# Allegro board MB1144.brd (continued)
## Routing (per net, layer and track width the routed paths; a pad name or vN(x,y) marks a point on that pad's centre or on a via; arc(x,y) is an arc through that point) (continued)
NETCN12_12: length 118.4
  TOP w0.127: CN12.12 109.32,81.15 109.69,81.52 U18.4 111.08,81.04 111.6,80.52 112.49,80.52 113.25,79.76 113.25,73.15 112.26,72.16 88.33,72.16 85.95,74.55 61.11,74.55 60.29,73.74 55.9,73.74 55.57,73.41 52.9,73.41 52.39,72.9 50.79,72.9 50.23,72.34 v1(50.21,72.34) ; v1(49.88,107.57) 49.75,107.7 SB26.2
  BOTTOM w0.127: v1(49.88,107.57) 51.94,105.51 51.94,94.28 49.88,92.23 49.88,84.96 51.94,82.91 51.94,76.86 50.21,75.13 v1(50.21,72.34)
NETCN12_14: length 18.2
  TOP w0.127: v1(110,71.45) 110,71.53 110.33,71.86 112.67,71.86 113.71,72.9 R162.1 ; v1(109.82,77.22) 110.19,76.85 U19.5 ; CN12.14 v1(109.32,79.88) R154.1
  BOTTOM w0.127: v1(110,71.45) 109.82,71.63 v1(109.82,77.22) 109.82,79.38 v1(109.32,79.88)
NETCN12_16: length 26.9
  TOP w0.127: U19.4 111.87,77.07 R156.1 110.33,78.61 v1(109.32,78.61) CN12.16 ; R131.1 113.96,89.59 113.96,89.92 112.82,91.06 111.19,91.06 110.56,90.42 107.92,90.42 v1(107.82,90.32)
  BOTTOM w0.127: v1(107.82,90.32) 107.26,89.76 107.26,81.18 109.32,79.12 v1(109.32,78.61)
NETCN12_18: length 116.3
  TOP w0.127: v1(49.47,73.58) 49.5,73.58 49.57,73.66 52.01,73.66 52.52,74.17 55.19,74.17 55.54,74.52 59.58,74.52 60.37,75.31 86.71,75.31 88.74,73.28 111.35,73.28 111.87,73.8 U19.3 111.87,75.55 111.47,75.95 109.95,75.95 108.55,77.34 107.41,77.34
  BOTTOM w0.127: v1(49.47,73.58) 49.52,73.63 49.52,75.64 49.93,76.05 49.93,84.15 49.37,84.71 49.37,92.94 49.9,93.47 49.9,101.83 49.24,102.49 49.24,107.95 51.4,110.11 55.85,110.11 57.15,111.41 57.15,111.99
NETCN12_20: length 112.5
  TOP w0.127: v1(48.81,73.58) 49.4,74.17 50.16,74.17 50.41,73.91 51.89,73.91 52.39,74.42 55.06,74.42 55.42,74.78 59.46,74.78 60.24,75.56 87.12,75.56 89.07,73.61 110.03,73.61 110.57,74.15 U19.1 110.57,75.45 110.33,75.69 109.44,75.69 109.06,76.07 CN12.20
  BOTTOM w0.127: SB39.2 55.21,111 54.71,110.49 51.02,110.49 48.86,108.33 48.86,102.49 49.65,101.7 49.65,93.6 49.12,93.07 49.12,84.58 49.68,84.02 49.68,76.43 49.07,75.82 49.07,73.84 v1(48.81,73.58)
NETCN13_1: length 13.3
  BOTTOM w0.508: JP15.6 12.97,77.77 7.11,77.77 6.78,78.11 3.91,78.11 CN13.1
NETCN13_2: length 211.7
  TOP w0.279: 19.4,94.87 19.52,94.75 U12.7
  TOP w0.381: U10.13 v1(107.58,107.97)
  TOP w0.508: 19.4,94.87 16.3,94.87 12.87,98.3 6.06,98.3 5.2,97.44 U11.3 3.09,97.44 2.41,96.75 2.41,90.35 1.29,89.23 1.29,76.45 2.31,75.44 3.78,75.44 CN13.2 ; v1(68.83,59.74) 40.33,59.74 37.51,56.92 28.06,56.92 v1(22.45,51.31)
  BOTTOM w0.508: CN13.2 10.46,76.96 11.45,75.97 11.45,68.91 12.92,67.44 12.92,64.52 22.45,54.99 v1(22.45,51.31) ; v1(68.83,59.74) 79.98,59.74 92.6,72.36 101.26,72.36 103.68,74.78 103.68,87.58 105.35,89.26 105.35,96.24 107.11,97.99 107.11,104.06 106.83,104.34 106.83,107.21 v1(107.58,107.97)
NETCN14_2: length 40.6
  TOP w0.127: CN18.3 17.61,51.32 R178.2 18.26,51.94 19.78,51.94 20.03,52.2 20.03,52.32 27.02,59.31 27.02,77.6 30.07,80.64 33.02,80.64
NETCN14_4: length 2.4
  TOP w0.127: R140.2 35.56,81.82 35.56,80.64
NETCN14_6: length 2.7
  TOP w0.127: R141.2 37.31,81.44 38.1,80.64
NETCN14_8: length 3.1
  TOP w0.127: 40.64,80.64 40.64,81.38 R142.2
NETCN14_10: length 46.2
  TOP w0.381: R158.1 13.61,77.77 17.11,77.77 18.71,79.38 26.44,79.38 33.34,86.28 38.65,86.28 40.1,84.84 40.1,83.69 43.15,80.64 43.18,80.64
  TOP w0.508: R158.1 12.16,76.58 JP15.5 JP15.3 JP15.1
NETCN14_12: length 2.9
  TOP w0.127: R143.2 45.72,81.82 45.72,80.64
NETCN14_14: length 2.9
  TOP w0.127: 48.26,80.64 48.26,81.82 R144.2
NETCN14_16: length 2.9
  TOP w0.127: 50.8,80.64 52.04,81.88 R145.2
NETCN14_18: length 2.8
  TOP w0.127: 53.34,80.64 53.34,82.07 R146.2
NETCN14_20: length 2.9
  TOP w0.127: R147.2 55.88,81.82 55.88,80.64
NETCN14_22: length 2.9
  TOP w0.127: R148.2 58.42,81.82 58.42,80.64
NETCN14_32: length 3
  TOP w0.127: R151.2 71.12,81.57 71.12,80.64
NETCN14_40: length 94.6
  TOP w0.127: U2.A1 82.9,150.74 82.9,146.38 85.67,143.61 88,143.61 90.11,141.5 v1(91.1,141.5) ; 81.28,80.64 82.04,80.64 82.92,81.53 85.34,81.53 87.45,83.64 87.45,85.24 88.49,86.28 88.49,90.42 87.98,90.93 v1(87.98,91.19)
  BOTTOM w0.127: v1(87.98,91.19) 88.23,91.19 89.38,92.33 93.82,92.33 98.14,96.65 98.14,99.44 100.11,101.41 100.11,109.41 100.68,109.98 100.68,135.03 98.16,137.54 94.66,137.54 91.1,141.1 v1(91.1,141.5)
NETCN14_42: length 92.7
  TOP w0.127: 83.82,80.64 84.96,80.64 87.83,83.52 87.83,85.14 89,86.31 89,90.3 89.5,90.81 v1(89.76,90.81) ; v1(92.04,141.63) 91.94,141.63 91.61,141.96 90.27,141.96 88.08,144.15 86.58,144.15 85.79,144.93 85.79,145.29 85.72,145.36 85.72,145.54 83.66,147.6 83.66,150.24 84.04,150.62 84.04,151.18 U2.B2
  BOTTOM w0.127: v1(89.76,90.81) 92.17,90.81 92.93,91.57 94.46,91.57 99.03,96.14 99.03,99.06 100.88,100.91 100.88,109.07 101.44,109.63 101.44,135.38 98.52,138.3 95.09,138.3 92.04,141.35 v1(92.04,141.63)
NETCN14_44: length 3.3
  TOP w0.127: R149.2 86.36,80.8 86.36,80.64
NETCN14_46: length 3.5
  TOP w0.127: R150.2 90.9,82.14 89.41,80.64 88.9,80.64
NETCN15_3: length 30.4
  TOP w0.127: v1(109.87,85.8) 110.19,86.12 RS1.6 ; R126.1 R131.2 118.71,86.36 CN15.3 122.02,84.99 122.02,80.9 121.25,80.14 113.66,80.14 112.74,81.05 112.74,82.04 111.87,82.92 U18.1 111.87,83.71 112.26,84.1 v1(112.26,84.33)
  BOTTOM w0.127: v1(109.87,85.8) 111.17,85.8 112.26,84.71 v1(112.26,84.33)
NETCN15_11: length 5.9
  TOP w0.127: R157.1 116.3,77.6 R159.2 CN15.11
NETCN15_17: length 4
  TOP w0.127: R163.2 CN15.17
NETCN15_19: length 4.1
  TOP w0.127: CN15.19 120.4,66.29 R164.2
NETCN17_2: length 6.3
  TOP w0.155: R180.2 112.68,50.36 113.19,50.36 113.81,50.98 113.81,51.58 114.34,52.11 115.61,52.11 115.76,51.96 115.76,51.28 115.46,50.98 CN17.2
NETCN17_3: length 8
  TOP w0.155: R177.2 R179.2 112.68,50.74 113.03,50.74 113.43,51.14 113.43,51.74 114.18,52.49 115.76,52.49 116.14,52.12 116.14,51.23 116.4,50.98 CN17.3
NETCN18_1: length 48.4
  TOP w0.127: CN18.1 17.54,53.52 R175.2 18.7,54.67 21.29,54.67 26.38,59.77 26.38,78.46 33.65,85.72 37.81,85.72 R142.1
NETCN18_2: length 47
  TOP w0.127: CN18.2 17.59,52.42 R176.2 18.26,53.09 20.34,53.09 26.77,59.51 26.77,78.36 33.78,85.37 36.52,85.37 R141.1
NETCN18_5: length 49.7
  TOP w0.127: R140.1 34.13,83.19 34.13,80.14 33.5,79.5 30.09,79.5 27.78,77.19 27.78,58.93 20.42,51.56 20.42,48.64 20.16,48.39 16.99,48.39 16.26,49.12 CN18.5
NETCN18_7: length 70.9
  TOP w0.127: R147.1 58.01,83.69 58.01,82.8 57.12,81.92 57.12,77.85 56.39,77.13 54.34,77.13 53.92,76.71 50.26,76.71 49.5,75.95 44.29,75.95 43.78,75.44 34.37,75.44 33.86,74.93 32.86,74.93 28.8,70.87 28.8,58.8 21.3,51.31 21.3,48.39 20.54,47.62 18.13,47.62 R182.2 17.42,46.92 CN18.7
NETCN18_8: length 71.9
  TOP w0.127: R148.1 58.52,83.44 58.52,82.68 57.5,81.66 57.5,77.85 56.51,76.86 54.45,76.86 54.04,76.45 50.39,76.45 49.63,75.69 44.42,75.69 43.91,75.18 34.64,75.18 34,74.55 32.99,74.55 29.05,70.61 29.05,58.67 21.56,51.18 21.56,48.01 20.16,46.61 18.26,46.61 R185.2 17.46,45.82 CN18.8
NETCN18_10: length 2.9
  TOP w0.127: R194.2 7.08,41.81 CN18.10
NETCN19_23: length 10.1
  TOP w0.127: T6.3 92.04,38.61 92.42,38.23 v1(92.93,38.23) 93.82,38.23 R259.2
  BOTTOM w0.127: v1(92.93,38.23) 96.48,34.68 CN19.23
NETCN19_31: length 12.5
  TOP w0.127: U32.16 98.76,20.44 99.66,21.34 99.66,23.58 CN19.31
NETCN19_32: length 16.2
  TOP w0.127: CN19.32 102.46,23.33 102.46,20.95 100.44,18.93 U32.13
NETCN19_33: length 8.7
  TOP w0.127: CN19.33 97.92,21.17 U32.1
NETCN19_34: length 11
  TOP w0.127: U32.15 91.79,19.93 91.92,20.07 99.35,20.07 CN19.34
NETCN20_2: length 3.5
  TOP w0.203: R192.2 124.43,42.42 125.95,40.9 CN20.2
NETCN20_3: length 4
  TOP w0.203: CN20.3 123.05,40.37 122.02,41.4 121.13,41.4 R191.1
NETCN21_2: length 3.5
  TOP w0.203: CN21.2 125.95,27.06 124.3,28.7 R221.1
NETCN21_3: length 4
  TOP w0.203: CN21.3 123.05,26.53 121.89,27.69 121.13,27.69 R220.1
NETCN21_4: length 44.4
  TOP w0.203: CN21.4 121.18,18.29 107.16,18.29 105.12,20.32 105.12,23.88 103.35,25.65 98.14,25.65 97.12,24.64 84.42,24.64 83.28,25.78 R227.1
NETCN21_6: length 25.7
  TOP w0.203: R225.2 90.39,25.27 96.74,25.27 97.63,26.16 113.66,26.16 CN21.6
NETCN22_1: length 10.5
  TOP w0.508: 9.44,21.59 CN22.1 ; CN22.1 11.83,21.59 ; CN22.1 10.64,19.3 ; CN22.1 10.64,23.88 ; U31.1 17.62,22.61 ; U31.1 17.62,21.65 ; U31.1 16.34,22.13 ; U31.1 18.9,22.13
NETCN23_2: length 3.4
  TOP w0.127: v1(69.69,27.36) U30.16
  BOTTOM w0.127: CN23.2 71.09,28.5 69.95,27.36 v1(69.69,27.36)
NETCN23_3: length 5.7
  TOP w0.127: U30.15 70.96,27.61 v1(69.69,26.34)
  BOTTOM w0.127: CN23.3 68.55,27.48 v1(69.69,26.34)
NETCN23_4: length 10.9
  TOP w0.127: v1(66.77,22.86) 69.69,19.94 U30.13
  BOTTOM w0.127: CN23.4 66.01,23.62 v1(66.77,22.86)
NETCN23_7: length 25.7
  TOP w0.127: v1(62.93,4.22) 62.93,10.64 64.36,12.06 66.39,12.06 68.04,13.72 68.04,17.14 67.15,18.03 U30.11
  BOTTOM w0.127: v1(62.93,4.22) 64.71,2.44 67.05,2.44 68.55,3.94 CN23.7
NETCN23_8: length 20.5
  TOP w0.127: v1(63.7,4.32) 63.7,10.41 64.84,11.56 66.77,11.56 68.42,13.21 68.42,19.21
  BOTTOM w0.127: CN23.8 66.01,3.95 66,3.94 64.08,3.94 v1(63.7,4.32)
NETCN23_18: length 13.5
  TOP w0.127: v1(58.39,23.62) 59.79,22.23 63.72,22.23 64.61,21.34 U30.9 64.61,17.78 R242.2
  BOTTOM w0.127: v1(58.39,23.62) CN23.18
NETD3_1: length 2.2
  TOP w0.127: R59.1 41.62,126.22 D3.1
NETD3_2: length 2.8
  TOP w0.127: D3.2 40.12,123.17 JP8.2
NETD4_1: length 2.2
  TOP w0.127: D4.1 JP9.2
NETD4_2: length 9.5
  TOP w0.127: R93.1 106.65,112.09 106.6,112.14 v1(106.6,112.17) 106.57,112.17 105.71,113.03 D4.2 ; U10.16 v1(106.6,107.97)
  BOTTOM w0.127: v1(106.6,112.17) 106.78,111.99 106.78,108.14 v1(106.6,107.97)
NETJP4_2: length 13.3
  TOP w0.127: JP4.2 17.49,137.54 R45.1 17.11,134.37 15.84,133.1 15.84,128.91 16.73,128.02 U8.8
NETJP4_3: length 2.9
  TOP w0.127: R46.1 20.03,138.68 JP4.3
NETJP5_1: length 144.2
  TOP w0.508: v1(111.42,126.92) 110.84,127.51 110.84,131.44 109.44,132.84 108.43,132.84 JP5.1
  BOTTOM w0.508: RV3.2 104.87,39.27 112.9,47.29 112.9,57.12 116.78,61.01 116.78,69.62 117.01,69.85 117.01,70.89 118.28,72.16 118.28,87.76 116.3,89.74 111.78,89.74 110.03,91.49 110.03,93.52 110.79,94.28 110.79,100.38 111.12,100.71 111.12,108.31 110.46,108.97 110.46,114.81 110.79,115.14 110.79,123.11 111.42,123.75 v1(111.42,126.92)
NETJP5_2: length 4.4
  BOTTOM w0.508: JP5.2 JP7.2
NETJP5_3: length 8.9
  TOP w0.508: R51.1 R52.2 JP5.3
NETJP6_1: length 3.2
  TOP w0.127: R55.2 JP6.1
NETJP7_1: length 2.4
  TOP w0.508: R63.1 JP7.1
NETJP10_2: length 6
  TOP w0.508: L1.1 94.96,104.65 JP10.2
NETJP11_4: length 63.5
  TOP w0.127: R123.1 55.21,90.17 54.34,89.3 U15.12 47.47,89.3 45.58,91.19 38.83,91.19 38.07,90.42 36.93,90.42 36.42,89.92 31.97,89.92 30.7,88.65 27.53,88.65 26.89,89.28 22.78,89.28 v1(22.68,89.19) ; R123.1 57.63,90.81 T2.5 T2.2 ; R123.1 57.31,89.86 T2.6 T2.1
  BOTTOM w0.127: v1(22.68,89.19) 19.83,92.04 19.83,96.72 19.15,97.41 19.15,102.87 17.88,104.14 JP11.4
NETJP12_2: length 66.4
  TOP w0.127: v1(18.13,102.74) 18.76,103.38 18.76,105.26 20.03,106.53 34.56,106.53 v1(34.66,106.43) ; U7.6 57.25,118.87 56.1,120.02 v1(55.34,120.02)
  BOTTOM w0.127: JP12.2 22.57,88.49 18.64,92.43 18.64,102.23 v1(18.13,102.74) ; v1(34.66,106.43) 35.5,106.43 42.61,113.54 48.86,113.54 v1(55.34,120.02)
NETJP13_2: length 75.2
  TOP w0.102: U5.B4 99.06,145.67 96.87,145.67
  TOP w0.127: JP13.2 R133.2 98.77,90.17 v1(97.5,91.44) ; v4(93.87,144.3) 95.09,144.3 96.46,145.67 96.87,145.67
  BOTTOM w0.127: v1(97.5,91.44) 97.5,93.34 100.04,95.89 100.04,98.81 101.67,100.43 101.67,108.53 102.2,109.07 102.2,135.74 98.88,139.06 95.6,139.06 93.06,141.6 93.06,143.79 93.57,144.3 v4(93.87,144.3)
NETJP14_1: length 92.2
  TOP w0.089: U29.C6 79.48,30.24 78.09,30.24 77.82,29.97
  TOP w0.127: 77.82,29.97 77.29,29.44 77.29,29.08 76.65,28.45 v1(76.55,28.45)
  BOTTOM w0.127: v1(76.55,28.45) 76.27,28.45 72.97,31.75 71.04,31.75 70.66,32.13 56.92,32.13 42.89,46.15 42.89,62.23 35.91,69.22 29.94,69.22 26.23,72.92 26.23,78.64 25.11,79.76 JP14.1
NETJP14_2: length 174.8
  TOP w0.127: v1(9.02,11.21) 9.96,12.15 U36.3 ; v1(94.71,13.69) 94.71,13.72 95.68,14.69 U35.3
  BOTTOM w0.127: v1(94.71,13.69) 92.75,13.69 89.6,10.54 30.19,10.54 27.27,7.62 18.84,7.62 14.37,12.09 10.66,12.09 9.79,11.21 v1(9.02,11.21) 9.02,13.5 14.07,18.54 14.07,20.95 26.89,33.78 26.89,67.31 22.07,72.14 22.07,75.95 21.56,76.45 21.56,81.28 JP14.2
NETJP15_2: length 147.4
  TOP w0.127: U10.17 106.7,107.32 107.66,106.35 v1(107.66,106.35) ; JP15.2 18.38,80.9 26.51,80.9 27.27,81.66 v1(27.27,81.97) ; v1(30.5,70.79) 31.59,71.88 50.41,71.88 51.17,72.64 52.52,72.64 53.03,73.15 55.7,73.15 56.03,73.48 60.42,73.48 61.23,74.3 85.54,74.3 88.59,71.25 v1(107.64,71.25)
  BOTTOM w0.127: v1(27.27,81.97) 27.35,81.89 27.35,74.35 30.5,71.2 v1(30.5,70.79) ; v1(107.66,106.35) 108.05,105.97 108.05,96.72 106.65,95.33 106.65,94.41 105.94,93.7 105.94,89.81 106.65,89.1 106.65,80.19 107.64,79.2 v1(107.64,71.25)
NETJP19_1: length 55
  TOP w0.127: R145.1 52.29,84.58 52.98,83.9 52.98,82.04 52.06,81.13 52.06,80.26 51.56,79.76 50.34,79.76 49.35,78.77 49.35,77.88 48.71,77.24 41.04,77.24 40,76.2 29.38,76.2 v1(29.36,76.23)
  BOTTOM w0.127: JP19.1 25.47,98.96 25.47,93.37 28.87,89.97 28.87,76.66 29.31,76.23 v1(29.36,76.23)
NETJP19_2: length 66.3
  TOP w0.127: R21.2 19.98,157.42 v1(20.67,157.42) U1.4
  BOTTOM w0.127: JP19.2 22.57,100.84 24.35,102.62 25.37,102.62 26.09,103.34 26.09,109.52 24.86,110.74 24.86,124.21 25.19,124.54 25.19,126.82 22.78,129.24 22.78,132.87 23.69,133.78 23.69,141.01 25.37,142.68 25.37,152.53 20.67,157.23 v1(20.67,157.42)
NETL4_2: length 3.6
  TOP w0.508: R223.2 R219.2 L4.2
NETLD1_2: length 2.5
  TOP w0.127: LD1.2 R258.2
NETLD2_2: length 2.5
  TOP w0.127: LD2.2 R257.2
NETLD3_2: length 2.5
  TOP w0.127: LD3.2 R256.2
NETLD4_2: length 2.5
  TOP w0.127: LD4.2 R255.2
NETLD5_1: length 1.6
  TOP w0.127: LD5.1 23.08,164.85 R6.2
NETLD5_2: length 2.9
  TOP w0.127: LD5.2 21.43,167.26 21.18,167.51 T1.3
NETLD6_1: length 1.3
  TOP w0.127: 22.96,162.43 LD6.1
NETLD6_2: length 125.7
  TOP w0.127: U1.3 21.37,159.83 20.8,160.4 v1(20.8,160.78) 20.8,161.67 21.43,162.43 LD6.2 ; R109.2 54.71,100.46 54.71,97.66 54.25,97.21 50.51,97.21 49.85,96.55 49.85,95.12 49.09,94.36 47.97,94.36 47.09,93.47 31.08,93.47 28.92,91.31 17.24,91.31 v1(17.11,91.44)
  BOTTOM w0.127: v1(17.11,91.44) 17.05,91.5 17.05,101.85 15.97,102.94 15.97,105.28 17.05,106.37 17.05,108.11 20.54,111.6 20.54,111.63 23.72,114.81 23.72,126.21 22.27,127.66 22.27,141.43 24.99,144.15 24.99,152.4 20.16,157.23 20.16,157.73 20.92,158.5 20.92,160.66 v1(20.8,160.78)
NETLD7_1: length 1.8
  TOP w0.127: R165.1 LD7.1
NETLD8_2: length 2
  TOP w0.127: LD8.2 18.01,7.38 R253.2
NETLD8_3: length 1.8
  TOP w0.127: R254.2 19.51,7.74 LD8.3
NETLD8_4: length 6.8
  TOP w0.127: LD8.4 19.51,4.2 18.64,5.08 17.37,5.08 16.86,5.59 16.86,7.75 R252.1
NETLD9_1: length 45.4
  TOP w0.127: R268.2 80.23,48.77 80.23,43.43 80.87,42.8 92.5,42.8 96.87,38.43 96.87,36.47 97.68,35.66 103.65,35.66 111.09,43.1 LD9.1
NETLD9_2: length 48.5
  TOP w0.127: LD9.2 109.57,42.42 103.12,35.97 97.92,35.97 97.2,36.69 97.2,38.56 92.58,43.18 81.12,43.18 80.74,43.56 80.74,47.24 81.12,47.62 U37.8 82.73,49.19 81.12,50.8 R110.2
NETR1_2: length 2.6
  TOP w0.127: R261.2 R1.2 23.49,166.12 T1.1
NETR18_1: length 9.9
  TOP w0.102: 83.28,155.07 83.28,154.19 U2.B5
  TOP w0.127: 83.28,155.07 80.74,157.61 R22.2 R18.1
NETR23_2: length 1.8
  TOP w0.127: U3.15 7.14,155.25 R23.2
NETR24_1: length 122.6
  TOP w0.127: v1(28.84,75.12) 29.64,75.12 30.47,75.95 40.25,75.95 41.29,76.99 48.91,76.99 49.63,77.7 49.63,78.61 50.44,79.43 54.25,79.43 54.58,79.76 54.58,81.15 55.34,81.92 55.34,83.57 R146.1 ; R24.1 v1(23.72,155.32)
  BOTTOM w0.127: v1(28.84,75.12) 28.77,75.18 28.77,75.64 28.37,76.05 28.37,89.64 24.78,93.22 24.78,97.23 23.72,98.3 23.72,100.46 26.34,103.08 26.34,109.64 25.11,110.87 25.11,123.98 25.47,124.33 25.47,127.13 23.11,129.49 23.11,132.82 24.07,133.78 24.07,140.85 25.75,142.52 25.75,152.73 23.72,154.76 v1(23.72,155.32)
NETR24_2: length 1.7
  TOP w0.127: R24.2 20.34,155.01 U4.15
NETR25_2: length 5
  TOP w0.102: 104.06,151.13 104.06,149.66 103.46,149.06 U5.F7
  TOP w0.127: 104.06,151.13 104.06,153.75 R25.2
NETR29_2: length 3.3
  TOP w0.254: U4.6 20.34,148.66 R31.1 21.18,147.83 R29.2
NETR30_2: length 9.4
  TOP w0.254: U4.5 19.69,149.14 18.89,148.34 R30.2 19.65,147.83 R31.2 ; U4.8 21.64,149.1 21.9,148.84 v1(21.94,148.84)
  BOTTOM w0.254: v1(21.94,148.84) 20.92,147.83 R30.2
NETR32_2: length 106.6
  TOP w0.102: 96.87,146.06 U5.A4
  TOP w0.127: v1(91.99,143.97) 92.75,143.97 R32.2 95.35,145.03 96.37,146.06 96.87,146.06 ; 46.83,131.84 46.83,145.67 v1(47.06,145.9) ; v1(88.61,141.73) 88.23,141.73 87.09,142.88 84.93,142.88 76.3,151.51 76.3,160.78 74.19,162.89 71.34,162.89 v1(69.98,164.25)
  BOTTOM w0.127: v1(47.06,145.9) 49.86,145.9 53.13,149.17 53.13,159.38 52.7,159.82 52.7,160.55 54.48,162.33 54.48,166.09 54.86,166.47 64.18,166.47 64.74,167.03 64.74,168.55 65.14,168.96 69.16,168.96 69.72,168.4 69.72,164.52 v1(69.98,164.25) ; v1(91.99,143.97) 91.99,143.36 90.37,141.73 v1(88.61,141.73)
NETR33_2: length 6.8
  TOP w0.127: U7.97 60.25,140.76 59.66,141.35 59.02,141.35 v1(58.77,141.1) 58.77,141.76 ; R33.2 58.01,142.49
  BOTTOM w0.127: 59.28,142.24 59.28,141.6 v1(58.77,141.1)
NETR34_1: length 198.8
  TOP w0.127: v1(35.2,107.42) 35.02,107.24 16.6,107.24 v1(15.85,106.49) ; v1(40.35,112.95) 40.35,117.98 37.18,121.16 37.18,129.03 44.93,136.78 44.93,146.94 46.83,148.84 56.74,148.84 59.28,146.3 62.07,146.3 62.45,145.92 62.58,145.92 R34.1 ; R189.1 59.91,43.69 57.37,43.69 55.59,41.91 50.95,41.91 46.98,45.87 31.57,45.87 29.81,47.62 v1(26.38,47.62) ; R119.2 26.13,92.84 25.62,92.33 18,92.33 17.37,92.96 16.61,92.96 v1(16.35,93.22)
  BOTTOM w0.127: v1(35.2,107.42) 35.2,107.96 40.19,112.95 v1(40.35,112.95) ; v1(26.38,47.62) 26.38,48.9 25.98,49.3 25.98,67.28 20.95,72.31 20.95,74.52 19.02,76.45 19.02,86.36 16.22,89.15 16.22,93.09 v1(16.35,93.22) 16.51,93.37 16.51,101.32 15.08,102.74 15.08,105.72 15.84,106.49 v1(15.85,106.49)
NETR35_1: length 176.8
  TOP w0.127: v1(40.86,103.89) 40.86,105.41 39.85,106.43 39.85,118.11 36.93,121.03 36.93,129.29 44.55,136.91 44.55,147.19 46.58,149.22 56.74,149.22 59.4,146.56 62.2,146.56 62.58,146.18 63.6,146.18 R35.1 ; R199.2 v1(83.03,39.24)
  BOTTOM w0.127: v1(40.86,103.89) 39.77,102.79 39.77,94.69 40.74,93.73 40.74,88.52 39.59,87.38 39.59,76.33 45.99,69.93 45.99,45.59 53.61,37.97 66.77,37.97 69.84,41.05 73.02,41.05 73.5,41.53 82.01,41.53 83.03,40.51 v1(83.03,39.24)
NETR36_2: length 7.4
  TOP w0.127: v1(60.73,143.18) 60.67,143.18 60.37,143.48 59.76,143.48 ; U7.96 60.75,140.77 59.79,141.73 59.79,141.99 ; 59.4,142.37 R36.2
  BOTTOM w0.127: R36.2 60.01,143.89 v1(60.73,143.18)
NETR37_1: length 1.9
  TOP w0.127: R37.1 61.18,143.51 61.18,142.37
NETR38_2: length 5
  TOP w0.127: 70.07,142.47 70.07,143.89 R38.2 ; 70.45,141.86 70.45,141.22 71.75,139.93 U7.74
NETR39_1: length 6.9
  TOP w0.127: 73.12,143.89 73.25,143.76 73.25,142.49 SB3.2 73.63,141.83 72.25,140.46 U7.73 ; R39.1 72.49,143.76 R40.1
NETR40_2: length 11.2
  TOP w0.127: TS1.1 71.34,149.73 71.34,145.03 R40.2
NETR41_2: length 10.3
  TOP w0.127: R41.2 R43.1 108.76,139.5 108.76,142.06 107.87,142.95 106.27,142.95 105.58,143.64 103.85,143.64 103.45,144.04 U5.F2
NETR42_2: length 4.2
  TOP w0.127: R42.2 121,140.34 SB7.1 120.31,138.37 U6.7
NETR48_2: length 9
  TOP w0.127: 82.14,137.29 81.5,137.92 79.22,137.92 78.96,137.67 78.96,137.41 R48.2 77.44,137.16 76.42,136.15 U7.70
NETR50_2: length 8.9
  TOP w0.127: U7.69 78.7,135.65 R50.2 78.71,135.89 79.22,136.4 80.87,136.4 81.63,135.64 SB9.2
NETR53_2: length 148.7
  TOP w0.127: R53.2 46.32,130.43 41.24,130.43 38.64,127.83 38.64,121.35 41.75,118.24 41.75,109.35 v1(42.13,108.97) ; R205.2 v1(88.11,35.31)
  BOTTOM w0.127: v1(42.13,108.97) 43.61,108.97 45.61,106.96 45.61,104.9 44.32,103.61 44.32,94.61 44.6,94.34 44.6,77.01 45.49,76.12 45.49,71.83 47.85,69.47 47.85,62.61 46.7,61.47 46.7,45.64 53.87,38.48 61.11,38.48 65.04,42.42 82.77,42.42 86.84,38.35 86.84,36.58 v1(88.11,35.31)
NETR54_2: length 231.2
  TOP w0.127: v1(93.41,93.42) 93.21,93.22 61.69,93.22 61.06,92.58 55.85,92.58 54.71,91.44 54.35,91.44 v1(54.2,91.29) ; v1(50.64,65.41) 50.01,64.77 43.28,64.77 39.72,68.33 31.96,68.33 30.55,66.91 v1(30.55,66.37) ; R258.1 v1(26.13,10.29) ; R54.2 81.06,131.25 81.06,131.38 82.14,132.46 84.04,132.46 89.88,138.3 v1(89.88,138.43)
  BOTTOM w0.127: v1(54.2,91.29) 53.97,91.06 53.97,85.85 54.45,85.37 54.45,75.56 51.33,72.44 51.33,67.74 50.64,67.06 v1(50.64,65.41) ; v1(30.55,66.37) 27.65,63.47 27.65,33.4 15.72,21.46 15.72,14.48 17.24,12.95 24.99,12.95 26.13,11.81 v1(26.13,10.29) ; v1(93.41,93.42) 93.41,95.08 96.36,98.03 96.36,107.59 100.17,111.4 100.17,133.6 98.83,134.95 95.9,134.95 92.42,138.43 v1(89.88,138.43)
NETR56_2: length 16.1
  TOP w0.127: 85.44,130.81 85.19,130.56 84.93,130.56 84.3,129.92 82.52,129.92 82.24,129.65 82.24,129.06 81.79,129.06 80.87,128.14 79.22,128.14 78.71,128.65 R56.2 77.69,127.89 77.69,125.73 76.61,124.65 U7.47
NETR59_2: length 115.6
  TOP w0.127: v1(107.59,105.64) 106.73,105.64 106.46,105.37 U10.20 ; R59.2 39.47,126.24 39.47,121.79 42.51,118.75 42.51,112.22 43.33,111.4 v1(43.33,110.82) ; v1(106.14,94.61) 105.94,94.82 95.8,94.82 93.95,92.96 61.82,92.96 61.18,92.33 55.98,92.33 54.45,90.81 53.05,90.81 52.7,91.16 48.46,91.16 48.1,90.81 v1(48.1,90.7)
  BOTTOM w0.127: v1(48.1,90.7) 48.1,92.48 47.11,93.47 47.11,106.06 43.35,109.82 43.35,110.8 v1(43.33,110.82) ; v1(107.59,105.64) 107.61,105.61 107.61,96.77 106.14,95.3 v1(106.14,94.61)
NETR62_2: length 15.2
  TOP w0.127: SB14.2 SB15.2 84.8,128.02 84.68,128.14 81.38,128.14 81.12,127.89 79.09,127.89 78.71,127.51 R62.2 77.95,126.36 77.95,125.6 76.49,124.15 U7.46
NETR64_2: length 9.1
  TOP w0.127: U7.45 76.37,123.65 77.95,125.22 78.71,125.22 ; 78.78,125.5 78.84,125.55 78.84,125.86 79.22,126.24 81.25,126.24 82.01,127
NETR65_2: length 12.4
  TOP w0.127: U7.44 76.55,123.15 78.12,124.71 81.76,124.71 82.14,125.09 R65.2 ; 82.26,125.73 82.65,126.11 85.06,126.11 SB17.2
NETR66_2: length 12.8
  TOP w0.127: SB19.2 81.38,124.46 79.09,124.46 78.71,124.08 R66.2 77.95,123.7 76.89,122.65 U7.43 ; 82.26,124.08 82.39,124.21 82.39,124.33 82.65,124.59 84.93,124.59 SB18.2
NETR67_2: length 79.9
  TOP w0.127: R67.2 47.09,122.05 45.43,122.05 v1(45.18,122.3) ; v1(31.34,111.12) 27.02,111.12 25.98,110.08 21.58,110.08 20.67,111 20.67,115.44 22.09,116.87 22.09,134.32 22.8,135.03 22.8,138.79 25.83,141.81 34.33,141.81 36.8,144.27 SW1.2
  BOTTOM w0.127: v1(45.18,122.3) 45.05,122.3 42.77,120.02 40.48,120.02 31.59,111.12 v1(31.34,111.12)
NETR68_2: length 12.6
  TOP w0.127: SB20.2 84.68,122.68 82.39,122.68 82.14,122.43 ; U7.42 74.33,122.17 R68.2 78.71,122.68 78.96,122.94 81.12,122.94 SB21.2
NETR71_1: length 4.6
  TOP w0.127: U9.1 108.64,117.86 107.03,117.86 R71.1 R74.2
NETR71_2: length 49.2
  TOP w0.127: R71.2 106.65,121.03 v1(106.65,121.54) ; SB8.1 87.34,140.59 101.06,140.59 101.57,140.08 102.84,140.08 104.36,138.56 106.78,138.56 106.9,138.68 109.52,138.68 v1(109.57,138.73)
  BOTTOM w0.127: v1(106.65,121.54) 107.28,122.17 107.28,126.11 105.89,127.51 105.89,135.89 106.14,136.14 107.16,136.14 109.57,138.56 v1(109.57,138.73)
NETR75_1: length 2.1
  TOP w0.127: U8.1 R75.1
NETR76_2: length 2.1
  TOP w0.127: R76.2 U8.4
NETR78_1: length 9.3
  TOP w0.254: U7.37 75.39,119.65 75.66,119.38
  TOP w0.508: 80.99,117.35 80.99,117.98 SB22.2 ; 75.66,119.38 78.2,116.84 81.12,116.84
NETR81_2: length 12.5
  TOP w0.127: U7.36 72.23,117.62 v1(72.23,118.75) 72.36,118.87 75.41,118.87 78.58,115.7 R81.2
  BOTTOM w0.127: 73.15,117.83 v1(72.23,118.75)
NETR82_2: length 12.3
  TOP w0.254: v1(72.1,116.33) 71.75,116.69 U7.35
  TOP w0.508: v1(72.1,116.33) 72.61,115.82 77.57,115.82 78.71,114.68 80.11,114.68 80.49,114.3 R82.2
  BOTTOM w0.508: v1(72.1,116.33) 73.37,116.33
NETR89_1: length 134.9
  TOP w0.127: R201.2 v1(88.11,36.58) ; R89.1 61.56,111.63 62.45,110.74 62.45,108.2 61.31,107.06 61.31,104.8 59.99,103.48 45.23,103.48 v1(44.88,103.12)
  BOTTOM w0.127: v1(44.88,103.12) 44.57,102.82 44.57,94.74 44.85,94.46 44.85,77.27 45.84,76.28 45.84,71.98 48.36,69.47 48.36,62.48 47.06,61.19 47.06,45.67 53.99,38.73 60.98,38.73 64.69,42.44 64.69,42.55 64.94,42.8 74.7,42.8 74.95,43.05 82.77,43.05 87.22,38.61 87.22,37.47 v1(88.11,36.58)
NETR90_1: length 153.1
  TOP w0.127: v1(64.23,110.74) 63.34,111.63 R90.1 ; v1(46.53,68.83) 50.51,68.83 51.02,68.33 54.2,68.33 54.96,69.09 65.25,69.09 v1(67.15,70.99) ; R208.2 v1(88.11,32.77)
  BOTTOM w0.127: v1(88.11,32.77) 86.46,34.42 86.46,38.23 82.52,42.16 70.6,42.16 66.66,38.23 53.74,38.23 46.32,45.64 46.32,68.63 v1(46.53,68.83) ; v1(64.23,110.74) 63.47,110.74 61.26,108.53 61.26,103.56 61.82,103 61.82,101.35 64.36,98.81 64.36,94.28 67.02,91.62 67.02,89.2 74.52,81.71 74.52,76.07 73.32,74.88 73.32,72.47 72.03,71.17 67.33,71.17 v1(67.15,70.99)
NETR91_1: length 44
  TOP w0.127: R127.2 80.54,88.7 U14.12 79.02,88.7 76.55,86.23 71.09,86.23 v1(70.71,86.61) ; R91.1 64.74,111 v1(64.99,110.74)
  BOTTOM w0.127: v1(64.99,110.74) 64.48,110.24 63.47,110.24 61.51,108.28 61.51,103.71 62.07,103.15 62.07,101.47 64.61,98.93 64.61,94.44 67.35,91.69 67.35,89.33 70.07,86.61 v1(70.71,86.61)
NETR97_2: length 18.1
  TOP w0.127: U7.26 67.25,116.39 70.71,112.93 70.71,110.49 72.36,112.14 74.52,112.14 v1(74.64,112.01)
  BOTTOM w0.127: 76.91,115.54 76.14,115.54 74.64,114.05 v1(74.64,112.01)
NETR98_2: length 18.2
  TOP w0.127: U7.27 67.75,116.37 71.34,112.78 74.9,112.78 75.41,112.27 v1(75.41,111.51) 73.25,111.51 R98.2
  BOTTOM w0.127: SB36.2 75.94,113.92 75.41,113.39 v1(75.41,111.51)
NETR99_2: length 16
  TOP w0.127: 73.76,110.62 74.01,110.87 75.79,110.87 v1(76.17,111.25) 76.17,112.52 75.28,113.41 71.22,113.41 68.25,116.38 U7.28
  BOTTOM w0.127: v1(76.17,111.25) 76.91,111.99 76.91,112.24
NETR103_1: length 10.2
  TOP w0.127: SB26.1 R103.1 51.15,113.28 54.75,116.88 U7.1
NETR104_1: length 123.8
  TOP w0.127: U7.2 55.25,116.75 51.91,113.41 51.91,111.12 R104.1 51.91,109.6 51.91,107.31 v1(50.26,105.66) ; R154.2 113,78.87 113,73.41 112.11,72.52 88.46,72.52 86.18,74.8 60.98,74.8 60.17,73.99 55.77,73.99 55.44,73.66 52.77,73.66 52.27,73.15 50.39,73.15 v1(49.57,72.34)
  BOTTOM w0.127: v1(49.57,72.34) 49.93,72.69 49.93,75.56 51.68,77.32 51.68,82.78 49.63,84.84 49.63,92.35 51.66,94.39 51.66,104.27 v1(50.26,105.66)
NETR105_1: length 133.5
  TOP w0.127: R105.1 60.55,104.8 59.76,104.01 45.56,104.01 42.89,106.68 v1(42.89,106.81) ; v1(82.39,39.24) 81.76,38.61 R198.2
  BOTTOM w0.127: v1(82.39,39.24) 82.39,40.34 81.58,41.15 73.63,41.15 73.22,40.74 70,40.74 66.85,37.59 53.61,37.59 45.54,45.67 45.54,69.82 39.21,76.15 39.21,87.76 40.43,88.98 40.43,93.6 39.47,94.56 39.47,103.38 v1(42.89,106.81)
NETR106_1: length 152.5
  TOP w0.127: R106.1 60.93,107.82 60.93,104.8 59.89,103.76 45.05,103.76 41.37,107.44 v1(41.37,107.7) ; v1(87.85,28.57) 87.73,28.57 87.34,28.19 R222.1
  BOTTOM w0.127: v1(87.85,28.57) 87.14,28.57 86.84,28.88 86.84,32.77 83.86,35.74 82.59,35.74 81.76,36.58 79.44,36.58 77.46,38.56 77.46,40.06 77.08,40.44 70.17,40.44 66.95,37.21 53.61,37.21 45.05,45.77 45.05,67.01 44.37,67.69 42.11,67.69 37.18,72.62 37.18,94.11 36.98,94.31 36.98,105.44 39.24,107.7 v1(41.37,107.7)
NETR107_1: length 197.2
  TOP w0.127: v1(59.91,9.14) 59.91,13.84 58.83,14.92 56.55,14.92 53.18,18.29 53.18,23.5 55.21,25.53 58.64,25.53 59.53,26.42 U30.24 ; R107.1 80.87,101.35 82.9,101.35 84.19,100.05 92.48,100.05 96.49,96.04 109.19,96.04 v1(109.87,95.35)
  BOTTOM w0.127: v1(59.91,9.14) 60.55,9.78 74.77,9.78 75.13,9.42 78.73,9.42 78.96,9.65 90.52,9.65 93.06,12.19 97.61,12.19 98.85,13.44 98.85,14.3 104.13,19.58 104.13,39.78 112.36,48.01 112.36,57.53 114.88,60.05 114.88,68.81 116.48,70.41 116.48,71.15 117.82,72.49 117.82,87.25 115.79,89.28 111.58,89.28 109.57,91.29 109.57,95.05 v1(109.87,95.35)
NETR112_2: length 2.2
  TOP w0.127: R112.2 6.68,99.34 U11.1
NETR113_1: length 3.3
  TOP w0.127: R113.1 5.81,96.65 5.81,95.76 5.59,95.54 U11.5
NETR114_1: length 3.3
  TOP w0.127: U12.3 24.22,95.25 R116.1 24.86,95.89 R114.1
NETR117_1: length 4.9
  TOP w0.127: R118.1 R119.1 24.99,93.47 R117.1 24.73,94.75 U12.2
NETR122_1: length 1.5
  TOP w0.127: U13.2 70.2,90.81 R122.1
NETR123_2: length 8.1
  TOP w0.127: T2.4 59.03,91.69 v1(58.01,91.69) R123.2 ; v1(58.01,86.74) 57.75,86.49 R135.1
  BOTTOM w0.127: v1(58.01,86.74) v1(58.01,91.69)
NETR125_1: length 4.2
  TOP w0.127: U15.14 51.23,90.6 51.53,90.3 R125.1 51.5,89.95 U15.13
NETR125_2: length 6.3
  TOP w0.127: U15.9 50.71,87.35 v1(50.99,87.63) R132.1 ; v1(52.17,90.55) 52.17,90.42 R125.2
  BOTTOM w0.127: v1(50.99,87.63) 51.02,87.63 51.28,87.88 51.28,89.66 v1(52.17,90.55)
NETR129_1: length 9.3
  TOP w0.127: U15.10 48.06,88 44.65,84.58 43.91,84.58 R129.1 R136.2
NETR129_2: length 7.9
  TOP w0.127: 44.29,85.22 44.93,85.86 44.93,89.95 ; U15.1 44.93,90.6 45.1,90.42 45.1,90.12 44.93,89.95 ; 44.93,89.95 U15.2
NETR130_1: length 2
  TOP w0.127: U14.11 81.04,88.05 R130.1
NETR132_2: length 20.5
  TOP w0.127: U15.8 50.47,86.7 50.77,87 51.91,87 52.55,87.63 R132.2 54.2,87.63 55.59,89.03 63.65,89.03 64.03,89.41 68.09,89.41 U13.1
NETR134_1: length 1.8
  TOP w0.127: R134.1 81.53,87.4 U14.10
NETR136_1: length 4.5
  TOP w0.127: U15.6 42.99,87.35 42.01,86.36 R136.1 42.26,86.11 42.64,86.11 43.23,86.7 U15.7
NETR137_1: length 23.4
  TOP w0.127: T3.6 T3.1 62.2,86.3 62.61,86.71 62.93,86.71 R137.1 63.21,87.25 T3.2 60.42,87.25 ; R144.1 49.68,84.58 51.07,85.98 53.75,85.98 55.02,87.25 55.02,88.07 55.72,88.77 60.09,88.77 60.42,88.44 60.42,87.25 ; 60.42,87.25 T3.5
NETR143_1: length 64.8
  TOP w0.127: R210.2 56.36,34.16 56.36,39.12 v1(59.02,41.78) ; R143.1 v1(47.85,84.58)
  BOTTOM w0.127: v1(47.85,84.58) 47.85,82.3 47.09,81.53 47.09,73.03 49.93,70.18 49.93,63.55 49.37,62.99 49.37,61.04 48.41,60.07 48.41,46.18 52.29,42.29 54.27,42.29 55.31,41.25 58.49,41.25 v1(59.02,41.78)
NETR156_2: length 115.6
  TOP w0.127: R156.2 112.62,77.85 112.62,73.53 112.01,72.92 88.51,72.92 86.38,75.06 60.62,75.06 59.81,74.24 55.65,74.24 55.31,73.91 52.65,73.91 52.14,73.41 49.96,73.41 49.19,72.64 48.84,72.64 v1(48.58,72.39)
  BOTTOM w0.127: v1(48.58,72.39) 48.3,72.67 48.3,75.44 49.42,76.56 49.42,83.9 48.86,84.45 48.86,93.19 49.4,93.73 49.4,101.57 48.48,102.49 48.48,108.58 50.9,111 53.05,111 SB40.2 53.72,111.66
NETR167_2: length 6.9
  TOP w0.127: T4.1 107.71,56.64 107.96,56.9 111.35,56.9 111.35,54.86
NETR168_1: length 1.5
  TOP w0.127: R168.1 64.62,56.27 U23.44
NETR172_2: length 3.6
  TOP w0.127: R172.2 59.53,54.23 59.53,53.47 60.2,52.8 U23.2
NETR174_2: length 2.8
  TOP w0.127: R174.2 60.19,52.3 U23.3
NETR177_1: length 4.3
  TOP w0.127: 111.35,52.07 109.3,52.07 T4.2
NETR184_1: length 2.1
  TOP w0.127: U37.5 R184.1
NETR187_1: length 1.8
  TOP w0.127: R187.1 66.12,45.1 U23.20
NETR188_1: length 4.2
  TOP w0.127: R188.1 59.72,45.15 59.72,45.28 61.02,46.58 U23.12
NETR189_2: length 2.9
  TOP w0.127: U25.2 61.95,42.67 61.56,43.05 61.56,43.81 R189.2
NETR193_2: length 1.1
  TOP w0.127: U25.3 61.82,42.17 61.56,41.91
NETR197_2: length 6.9
  TOP w0.089: U29.G2 81.98,32.74 81.98,33.25 82.25,33.53
  TOP w0.127: R197.2 84.8,37.21 84.8,36.58 83.53,35.31 83.53,34.81 82.25,33.53
NETR198_1: length 6
  TOP w0.089: U29.E4 80.48,31.74 80.48,32.09 80.49,32.1 80.49,32.39 80.48,32.39 80.48,33.53
  TOP w0.127: R198.1 81.76,36.55 80.49,35.27 80.49,33.53
NETR199_1: length 5.1
  TOP w0.089: U29.G3 81.48,32.74 81.48,33.53
  TOP w0.127: R199.1 83.03,36.32 81.48,34.78 81.48,33.53
NETR200_1: length 8.1
  TOP w0.127: U29.D5 v2(80.48,31.24) U29.D4 ; R200.1 83.92,36.45 82.08,34.61 82.08,33.98 v1(81.99,33.9)
  BOTTOM w0.127: v2(80.48,31.24) 80.97,31.73 81.47,31.73 81.88,32.14 81.88,33.78 81.99,33.89 v1(81.99,33.9)
NETR201_1: length 5.8
  TOP w0.127: U29.G1 82.24,32.49 82.87,33.12 83.45,33.12 84.22,33.89 84.22,35.36 R201.1
NETR202_2: length 1.6
  TOP w0.457: U28.3 49.06,36.13 R202.2
NETR203_1: length 3.4
  TOP w0.457: U28.5 R204.2 R203.1
NETR205_1: length 5.9
  TOP w0.089: 82.65,32.38 82.5,32.24 81.98,32.24 U29.F2
  TOP w0.127: R205.1 84.8,35.31 84.52,35.02 84.52,33.67 83.67,32.81 83.07,32.81 82.65,32.38
NETR206_1: length 1.6
  TOP w0.457: U28.1 49.06,34.23 R206.1
NETR208_1: length 4.8
  TOP w0.089: 82.65,31.62 82.53,31.74 81.48,31.74 U29.E3
  TOP w0.127: 82.65,31.62 83.15,31.62 83.54,32.01 84.69,32.01 R208.1
NETR210_1: length 2.8
  TOP w0.127: R210.1 56.99,30.73 U30.26
NETR211_2: length 20.4
  TOP w0.127: U30.28 54.58,28.93 v1(54.58,30.48) R211.2
  BOTTOM w0.127: TP14.1 50.26,16.13 53.05,18.92 53.05,25.15 54.58,26.67 v1(54.58,30.48)
NETR212_2: length 19.6
  TOP w0.127: U30.27 v1(55.72,30.48) 55.72,30.99 R212.2
  BOTTOM w0.127: TP15.1 53.56,24.77 55.72,26.92 v1(55.72,30.48)
NETR213_1: length 32.4
  TOP w0.127: v1(67.41,24.51) 62.83,24.51 60.8,26.54 U30.23 60.8,31.24 R213.1 ; v1(84.55,19.81) U33.10
  BOTTOM w0.127: v1(84.55,19.81) 84.55,19.81 83.15,21.21 76.8,21.21 76.04,21.97 69.95,21.97 v1(67.41,24.51)
NETR214_2: length 34.9
  TOP w0.127: v1(83.41,17.14) 83.13,17.14 82.88,17.4 U33.6 ; R214.2 64.74,30.61 v1(64.61,30.48) U30.20
  BOTTOM w0.127: v1(83.41,17.14) 82.52,16.26 69.44,16.26 63.6,22.1 63.6,29.46 v1(64.61,30.48)
NETR215_2: length 35.7
  TOP w0.127: 65.88,28.8 65.75,28.93 v1(65.75,30.35) R215.2 ; v1(84.55,17.91) 84.15,18.31 U33.7
  BOTTOM w0.127: v1(84.55,17.91) 84.3,17.65 82.52,17.65 81.5,16.64 70.2,16.64 63.98,22.86 63.98,28.57 v1(65.75,30.35)
NETR216_2: length 26.5
  TOP w0.127: U30.1 v1(54.45,20.95) ; R216.2 v1(66.77,30.48)
  BOTTOM w0.127: v1(66.77,30.48) 66.01,31.24 63.72,31.24 63.09,30.61 63.09,20.83 61.69,19.43 55.98,19.43 v1(54.45,20.95)
NETR217_2: length 3.9
  TOP w0.127: R218.1 R217.2 67.79,30.23 67.15,29.59 U30.18
NETR222_2: length 5.4
  TOP w0.089: U29.D3 81.48,30.74 82.64,30.74 82.65,30.73
  TOP w0.127: 82.65,30.73 83.03,30.73 84.8,28.96 84.8,28.83 R222.2
NETR228_2: length 20
  TOP w0.127: U32.2 89.88,21.97 R229.2 v1(90.14,22.99) R228.2 ; U33.22 v1(78.84,19.31)
  BOTTOM w0.127: v1(78.84,19.31) 79.98,18.16 83.79,18.16 84.17,18.54 87.22,18.54 88.23,19.56 88.23,22.1 89.12,22.99 v1(90.14,22.99)
NETR230_2: length 3
  TOP w0.127: R231.2 R230.2 80.38,22.84 U33.18
NETR232_2: length 3.3
  TOP w0.127: R232.2 77.57,19.43 R233.2 78.19,18.81 U33.23
NETR234_2: length 1.6
  TOP w0.457: R234.2 50.07,18.6 U34.3
NETR235_1: length 3.4
  TOP w0.457: R235.1 R236.2 U34.5
NETR235_2: length 16.2
  TOP w0.508: R235.2 39.21,19.18 35.15,15.11 RV1.1
NETR237_2: length 3.3
  TOP w0.127: U33.24 78.22,18.31 R237.2 77.82,16.76 R243.2
NETR238_1: length 3
  TOP w0.127: U35.2 95.68,15.54 95.09,16.13 95.09,16.87 95.5,17.27 R238.1
NETR239_1: length 1.5
  TOP w0.127: R239.1 88.88,17.41 U32.9
NETR240_1: length 1.6
  TOP w0.457: U34.1 50.07,16.7 R240.1
NETR241_1: length 39.4
  TOP w0.127: v1(85.31,17.78) 84.3,18.8 83.59,18.8 U33.8 ; v1(58.26,16.89) 57.37,16.89 R241.1 56.99,17.27 U30.3
  BOTTOM w0.127: v1(58.26,16.89) 60.04,18.67 64.48,18.67 69.82,13.34 84.3,13.34 85.31,14.35 v1(85.31,17.78)
NETR255_1: length 76.9
  TOP w0.127: U32.11 89.88,17.53 v1(90.65,16.76) ; R255.1 v1(21.56,10.16)
  BOTTOM w0.127: v1(21.56,10.16) 23.21,8.51 26.51,8.51 30.19,12.19 88.11,12.19 90.65,14.73 v1(90.65,16.76)
NETR257_1: length 71
  TOP w0.127: v1(87.09,17.91) 87.1,17.91 87.36,18.16 87.36,18.81 87.48,18.93 U32.8 ; v1(24.61,10.16) R257.1
  BOTTOM w0.127: v1(24.61,10.16) 25.24,9.53 26.26,9.53 29.69,12.95 85.82,12.95 86.96,14.1 86.96,17.78 v1(87.09,17.91)
NETR260_1: length 20.3
  TOP w0.127: v1(84.8,20.57) 84.54,20.31 U33.11 ; R260.1 v1(88.87,35.31)
  BOTTOM w0.127: v1(84.8,20.57) 85.44,21.21 86.71,21.21 87.22,21.72 87.22,22.73 89.38,24.89 89.38,27.43 88.87,27.94 v1(88.87,35.31)
NETR260_2: length 2.4
  TOP w0.127: R267.1 R260.2 89.93,36.75 T6.1
NETR263_2: length 4.9
  TOP w0.127: R265.1 121.89,135.38 120.75,135.38 R263.2 119.05,137.07 U6.5
NETR264_2: length 4.7
  TOP w0.127: U6.6 119.8,137.72 R264.2 120.87,138.18 121.76,138.18 R266.1
NETSB9_1: length 42.5
  TOP w0.127: U9.6 111.47,126.24 111.92,126.68 111.92,128.21 113.13,129.41 113.13,131.44 110.84,133.73 110.84,135.13 111.35,135.64 111.35,136.27 110.59,137.03 107.92,137.03 107.41,137.54 103.85,137.54 102.33,139.06 100.81,139.06 100.43,139.45 88.23,139.45 84.04,135.25
NETSB12_1: length 40.7
  TOP w0.127: U9.5 112.74,127.64 113.61,128.5 113.61,131.75 v1(112.62,132.74) ; v1(110.51,135.99) 110.23,136.27 103.6,136.27 101.95,137.92 99.79,137.92 99.28,138.43 91.87,138.43 90.39,136.96 90.39,136.02 87.34,132.97 87.34,131.19
  BOTTOM w0.127: v1(112.62,132.74) 112.11,132.74 111.09,133.76 111.09,135.41 v1(110.51,135.99)
NETSB14_1: length 67.2
  TOP w0.127: 87.23,129.04 88.11,129.04 89.76,130.68 89.76,133.73 v1(90.77,134.75) ; v1(96.36,109.09) 102.71,109.09 103.35,109.73 106.01,109.73 106.39,109.35 108.3,109.35 110.46,111.51 112.24,111.51 112.87,112.14 112.87,114.55 110.2,117.22 U9.2
  BOTTOM w0.127: v1(96.36,109.09) 99.28,112.01 99.28,132.92 98.14,134.06 94.23,134.06 93.54,134.75 v1(90.77,134.75)
NETSB18_1: length 48.6
  TOP w0.127: SB18.1 88.74,124.08 91.15,121.67 91.15,115.82 90.39,115.06 90.39,113.41 92.68,111.12 v1(94.46,111.12) ; v1(95.22,109.09) 95.98,108.33 102.97,108.33 103.73,109.09 105.63,109.09 106.01,108.71 108.93,108.71 110.99,110.77 112.44,110.77 113.51,111.84 113.51,114.94 111.47,116.97 U9.3
  BOTTOM w0.127: v1(95.22,109.09) 95.22,110.36 v1(94.46,111.12)
NETSB21_1: length 50.7
  TOP w0.127: 83.92,121.67 84.42,121.16 89.88,121.16 90.14,120.9 90.14,116.33 88.87,115.06 88.87,114.17 92.68,110.36 94.71,110.36 94.84,110.49 101.82,110.49 103.47,112.14 103.47,113.74 104.18,114.45 107.31,114.45 v1(107.89,115.04) ; U9.7 110.2,126.11 v1(109.59,126.72)
  BOTTOM w0.127: v1(109.59,126.72) 109.59,125.76 109.14,125.3 109.14,116.28 v1(107.89,115.04)
NETT3_3: length 10
  TOP w0.127: v1(66.99,88.42) U16.4 66.31,87.77 65.88,88.2 T3.3 ; U13.4 66.39,90.85 v1(66.39,90.81)
  BOTTOM w0.127: v1(66.99,88.42) 66.97,88.42 66.24,89.16 66.24,90.65 v1(66.39,90.81)
NETTP19_1: length 50.5
  TOP w0.127: U23.21 v1(66.62,47.38)
  BOTTOM w0.127: TP19.1 91.65,70.37 80.33,59.05 68.55,59.05 66.74,57.25 66.74,51.36 66.16,50.77 66.16,47.68 66.46,47.38 v1(66.62,47.38)
NETU14_3: length 6.9
  TOP w0.127: U16.2 71.09,87.12 72.76,88.8 72.76,89.76 73,90 U14.3
NETU23_13: length 5.3
  TOP w0.127: U23.13 62.62,45.3 64.48,43.43 64.48,42.93 64.74,42.67 U25.7
OPAMP1_INM: length 21.9
  TOP w0.508: 91.44,80.64 91.54,80.64 94.84,83.95 94.84,90.42 96.49,92.08 97.89,92.08 99.16,90.81 R121.2 R120.1 102.2,91.18 RV2.1
OPAMP1_INP: length 40.7
  TOP w0.508: 107.03,126.36 107.03,125.98 v1(106.65,125.6) ; v1(105.89,112.14) 104.24,112.14 102.08,109.98 94.96,109.98 94.84,109.86 92.55,109.86 89.5,112.9 84.68,112.9 84.17,112.39 R83.2
  BOTTOM w0.508: v1(106.65,125.6) 105.89,124.84 v1(105.89,112.14)
OPAMP1_OUT: length 50.3
  TOP w0.508: R111.1 76.8,101.85 83.28,101.85 84.45,100.69 92.65,100.69 96.84,96.49 110.86,96.49 111.6,95.76 TP9.1 RV2.2 106.99,93.48 RV2.3
OSC_IN: length 10.1
  TOP w0.203: X3.2 53.82,52.58 54.58,51.82 58.13,51.82 C88.2 59.92,51.3 U23.5
OSC_OUT: length 11.6
  TOP w0.203: U23.6 59.15,50.8 C89.2 58.13,50.55 54.96,50.55 53.82,49.4 X3.1
PA0: length 36.8
  TOP w0.127: CN7.37 96.01,113.79 v1(96.67,114.45) ; 80.97,112.55 81.76,113.33 v1(82.19,113.33) 82.26,113.41 85.19,113.41 87.09,115.32 v1(87.6,115.32)
  TOP w0.254: 71.09,115.95 71.09,116.46 71.25,116.62 U7.34
  TOP w0.508: R83.1 79.22,113.92 78.45,113.92 77.18,115.19 71.85,115.19 71.09,115.95
  BOTTOM w0.127: 82.39,115.82 82.39,113.54 v1(82.19,113.33) ; v1(96.67,114.45) 95.5,113.28 93.06,113.28 92.42,113.92 92.42,115.19 91.92,115.7 89.5,115.7 89.38,115.57 87.85,115.57 v1(87.6,115.32)
PA4: length 31.6
  TOP w0.127: U7.40 75.8,121.15 76.68,120.27 v1(77.57,120.27) 78.2,119.63 R73.1 ; v1(98.04,116) 97.99,115.95 97.99,115.39 98.27,115.11 98.27,114.68 99.16,113.79 CN7.38
  BOTTOM w0.127: v1(77.57,120.27) 86.96,120.27 88.36,118.87 92.45,118.87 95.98,115.34 97.38,115.34 v1(98.04,116)
PA5: length 28.4
  TOP w0.127: U7.41 76.06,121.65 76.8,120.9 v1(77.57,120.9) R69.1 ; CN7.35 95.98,115.06 96.77,115.85 v1(96.79,115.85)
  BOTTOM w0.127: v1(77.57,120.9) 86.84,120.9 88.49,119.25 92.55,119.25 95.95,115.85 v1(96.79,115.85)
PA11: length 74.6
  TOP w0.155: v1(28.52,132.87) 29.76,134.11 CN6.6 ; R3.2 28.29,164.59 29.18,164.59 29.44,164.85 D1.D3 29.63,164.79 29.63,163.57 v1(29.35,163.29) ; v1(57.33,137.79) 57.19,137.93 57.19,138.5 57.25,138.56 U7.103
  BOTTOM w0.155: v1(29.35,163.29) 29.63,163.01 29.63,142.03 26.26,138.66 26.26,134.57 27.4,133.43 28.61,133.43 28.75,133.29 28.75,133.07 28.54,132.87 v1(28.52,132.87) 28.7,132.68 28.7,132.12 29.15,131.67 30.09,131.67 35.2,136.78 56.74,136.78 57.19,137.23 57.19,137.65 v1(57.33,137.79)
PA12: length 76
  TOP w0.155: v1(56.67,137.79) 56.81,137.93 56.81,138.48 56.75,138.54 U7.104 ; v1(29.41,132.82) 28.92,132.33 28.16,132.33 27.65,132.84 CN6.7 ; R4.2 31.97,163.96 30.83,163.96 30.45,164.34 30.45,164.47 30.07,164.84 D1.C3 30.01,164.79 30.01,163.57 v1(30.3,163.29)
  BOTTOM w0.155: v1(30.3,163.29) 30.01,163.01 30.01,141.87 26.64,138.5 26.64,134.73 27.56,133.81 28.77,133.81 29.13,133.45 29.13,133.1 v1(29.41,132.82) 29.08,132.49 29.08,132.28 29.31,132.05 29.93,132.05 30.82,132.94 30.82,133.32 31.04,133.54 31.42,133.54 31.63,133.75 31.63,134.13 31.85,134.35 32.23,134.35 32.45,134.57 32.45,134.94 32.67,135.16 33.04,135.16 35.04,137.16 52.56,137.16 52.76,137.36 53.07,137.36 53.27,137.16 53.58,137.16 53.79,137.36 54.1,137.36 54.3,137.16 54.61,137.16 54.81,137.36 55.12,137.36 55.33,137.16 56.58,137.16 56.81,137.39 56.81,137.65 v1(56.67,137.79)
PA13: length 274.1
  TOP w0.127: U24.7 72.1,48.11 72.1,47.5 71.74,47.14 v1(71.74,47.12) 71.6,47.12 70.83,47.88 70.83,48.39 70.43,48.8 U23.27 ; v1(28.16,134.62) 27.65,134.11 CN6.5 24.35,134.11 22.85,132.61 22.85,116.38 21.61,115.14 21.61,111.66 v1(22.02,111.25) ; v1(113.07,88.77) 113.07,88.72 112.47,88.12 RS1.13 ; v1(38.45,67.56) 44.55,61.47 v1(48.41,61.47) ; U7.105 56.25,140.34 v1(56.23,140.36)
  BOTTOM w0.127: v1(28.16,134.62) 27.53,135.25 27.53,137.92 28.72,139.12 54.76,139.12 55.34,139.7 55.57,139.7 v1(56.23,140.36) ; v1(22.02,111.25) 22.02,110.95 21.15,110.08 21.15,103.2 20.03,102.08 20.03,97.56 22.14,95.45 22.14,92.33 26.23,88.24 26.23,79.32 26.61,78.94 26.61,73.18 30.19,69.6 36.42,69.6 v1(38.45,67.56) ; v1(113.07,88.77) 115.36,88.77 117.44,86.69 117.44,72.67 114.04,69.27 114.04,60.35 111.6,57.91 111.6,49.78 108.3,46.48 97.25,46.48 95.09,48.64 74.14,48.64 72.61,47.12 71.74,47.12 v1(71.74,47.12) 71.61,47.25 70.5,47.25 68.83,48.92 68.24,48.92 67.91,48.58 67.91,48.17 68.09,47.98 68.32,47.98 68.52,47.78 68.52,46.76 67.89,46.13 62.83,46.13 61.03,44.32 61.03,41.63 59.79,40.39 54.32,40.39 53.18,41.53 51.91,41.53 47.47,45.97 47.47,60.53 v1(48.41,61.47)
PA14: length 276.7
  TOP w0.127: v1(39.64,67.08) 44.75,61.98 48.58,61.98 v1(48.74,62.13) ; v1(33.5,133.6) 32.73,132.84 CN6.8 ; v1(57.73,136.47) 57.6,136.35 56.92,136.35 56.11,137.15 U7.109 ; v1(24.33,131.62) 24.33,131.57 23.54,130.78 23.54,116.51 21.99,114.96 21.99,111.99 22.42,111.56 22.52,111.56 22.83,111.25 v1(22.83,110.9) ; U23.26 69.56,48.13 68.95,48.13 68.8,47.98 67.97,47.98 67.58,48.37 v1(67.58,48.92) 67.48,49.02 64.18,49.02 63.62,48.47 U23.15 ; RS1.11 112.5,87.62 112.62,87.73 112.64,87.73 112.97,88.06 v1(113.15,88.06)
  BOTTOM w0.127: v1(24.33,131.62) 24.83,132.13 27.76,132.13 28.9,130.99 30.88,130.99 v1(33.5,133.6) 35.91,136.02 56.99,136.02 57.37,136.4 57.65,136.4 v1(57.73,136.47) ; v1(48.74,62.13) 48.94,61.93 48.94,61.21 47.97,60.25 47.97,46.15 52.22,41.91 53.66,41.91 54.78,40.79 59.51,40.79 60.57,41.86 60.57,44.42 62.66,46.51 66.8,46.51 67.51,47.22 67.51,48.84 v1(67.58,48.92) 68.07,49.4 68.9,49.4 70.05,48.26 72.99,48.26 73.76,49.02 95.4,49.02 96.08,48.34 109.39,48.34 111.22,50.16 111.22,59.05 111.6,59.44 111.6,67.44 116.55,72.39 116.55,83.34 115.23,84.66 115.23,87.5 114.67,88.06 v1(113.15,88.06) ; v1(39.64,67.08) 36.7,70.03 30.5,70.03 27.02,73.51 27.02,81.31 26.66,81.66 26.66,88.52 22.52,92.66 22.52,95.66 20.47,97.71 20.47,101.93 21.61,103.07 21.61,109.68 v1(22.83,110.9)
PB2: length 34.7
  TOP w0.127: CN7.13 96.59,129.03 v1(96.82,128.8) ; 82.26,130.94 80.99,129.67 79.47,129.67 R54.1 77.44,129.16 v1(77.44,128.7) 77.44,125.86 76.68,125.09 75.38,125.09 75.33,125.15 U7.48
  BOTTOM w0.127: v1(77.44,128.7) 77.62,128.52 95.85,128.52 96.13,128.8 v1(96.82,128.8)
PB6: length 59.2
  TOP w0.127: CN6.40 30.45,112.52 v1(29.69,111.76) ; v1(28.04,96.77) 26.89,97.92 22.45,97.92 22.07,97.54 22.07,93.6 R118.2 ; v1(50.95,123.44) 51.15,123.65 U7.136
  BOTTOM w0.127: v1(50.95,123.44) 50.31,124.08 42.13,124.08 41.75,123.7 41.75,122.05 41.24,121.54 38.45,121.54 30.32,113.41 30.32,112.39 v1(29.69,111.76) 29.02,111.09 29.02,100.67 28.16,99.81 28.16,96.9 v1(28.04,96.77)
PC3: length 55.5
  TOP w0.127: v1(98.04,116.76) 98.49,116.31 98.49,115.72 99.16,115.06 CN7.36 ; R94.1 76.8,111 76.8,112.9 75.66,114.05 71.09,114.05 68.75,116.38 U7.29 68.75,118.8 67.41,120.14 v1(67.15,120.14)
  BOTTOM w0.127: v1(67.15,120.14) 67.28,120.27 67.28,121.67 67.91,122.3 86.07,122.3 88.74,119.63 92.81,119.63 96.13,116.31 97.58,116.31 v1(98.04,116.76)
PC13: length 182.2
  TOP w0.127: R80.2 36.93,109.02 v1(36.47,108.56) 35.96,108.05 19.93,108.05 v1(19.81,107.92) ; U7.7 57.75,119.13 56.1,120.78 v1(55.34,120.78) ; R244.2 v1(72.87,14.86)
  BOTTOM w0.127: v1(36.47,108.56) 36.98,108.56 42.34,113.92 48.61,113.92 54.83,120.14 54.83,120.4 55.21,120.78 v1(55.34,120.78) ; v1(72.87,14.86) 71.98,15.75 68.04,15.75 64.74,19.05 55.21,19.05 53.94,20.32 53.94,24.13 56.36,26.54 56.36,30.97 55.78,31.55 55.28,31.55 54.3,32.53 54.3,33.76 41.88,46.18 41.88,52.98 38.83,56.03 38.83,62.61 34.09,67.36 29.54,67.36 24.02,72.87 24.02,89.61 21.76,91.87 21.76,95.28 19.65,97.38 19.65,103 19.07,103.58 19.07,107.19 v1(19.81,107.92)
PC14: length 7
  TOP w0.127: R87.2 57.75,113.54 v1(57.75,114.3) 57.75,114.94 58.25,115.43 U7.8
  BOTTOM w0.127: 58.26,112.14 57.88,112.52 57.88,114.17 v1(57.75,114.3)
PC15: length 6.2
  TOP w0.127: U7.9 58.75,116.82 58.62,116.69 58.62,114.91 v1(58.39,114.68) 58.39,114.17 R88.2
  BOTTOM w0.127: v1(58.39,114.68) 58.52,114.81 SB33.1
PD3: length 80.4
  TOP w0.127: CN6.15 28.34,127.76 v1(28.37,127.79) ; 8.73,155.32 9.62,156.21 v1(26.64,156.21) ; v1(51.28,133.48) 51.61,133.15 U7.117
  BOTTOM w0.127: v1(51.28,133.48) 51.02,133.73 38.2,133.73 32.89,128.42 29,128.42 v1(28.37,127.79) 25.93,127.79 23.79,129.92 23.79,132.54 24.83,133.58 24.83,140.13 26.64,141.94 v1(26.64,156.21)
PD4: length 205.6
  TOP w0.102: v4(103.96,144.54) 104.44,144.06 U5.G2
  TOP w0.127: U7.118 51.53,132.65 51.02,132.14 v1(51.02,131.95) ; U21.43 55.39,70.41 54.58,69.6 54.58,69.09 54.2,68.71 51.07,68.71 50.18,69.6 34,69.6 v1(32.99,70.61) ; CN6.18 v1(29.69,126.49) ; v4(79.72,153.67) 82.14,151.26 82.52,151.26 82.79,151.53 U2.A2
  BOTTOM w0.127: v1(32.99,70.61) 29.39,74.21 29.39,75.45 28.62,76.23 28.62,89.77 25.19,93.2 25.19,97.59 24.1,98.68 24.1,100.2 24.99,101.09 25.8,101.09 26.85,102.14 26.85,109.9 25.75,111 25.75,123.39 28.24,125.88 28.44,125.88 29.05,126.49 v1(29.69,126.49) 32.86,126.49 38.83,132.46 48.36,132.46 48.86,131.95 v1(51.02,131.95) 53.05,131.95 53.82,131.19 57.75,131.19 59.4,132.84 65.53,132.84 72.46,139.78 73.3,139.78 75.94,142.42 75.94,143.92 76.42,144.4 76.42,151.13 78.96,153.67 v4(79.72,153.67) 79.98,153.92 79.98,154.81 81.12,155.96 87.37,155.96 87.98,156.57 87.98,157.18 91.59,160.78 97.61,160.78 100.68,157.71 100.68,155.47 101.39,154.76 101.39,153.72 102.05,153.06 102.05,151.94 102.97,151.03 102.97,149.07 103.35,148.69 103.35,145.15 v4(103.96,144.54)
PD5: length 213.7
  TOP w0.102: U5.A5 98.39,147.12 v4(97.83,147.12)
  TOP w0.127: U21.44 54.89,70.29 54.32,69.72 54.32,69.22 54.07,68.96 51.33,68.96 50.44,69.85 34.39,69.85 v1(33.62,70.61) ; U2.G5 87.58,153.78 87.98,154.18 88.49,154.18 88.67,154.36 88.67,154.91 v5(88.61,154.97) ; CN6.19 v1(28.42,125.22) ; v1(51.4,131.44) 51.4,131.7 51.91,132.21 52.64,132.21 U7.119
  BOTTOM w0.127: v1(33.62,70.61) 29.83,74.41 29.83,76.39 29.13,77.09 29.13,90.17 25.76,93.54 25.76,98.06 26.13,98.42 26.13,100.97 27.1,101.95 27.1,110.2 26,111.3 26,122.81 v1(28.42,125.22) 29.08,125.88 32.76,125.88 38.96,132.08 48.36,132.08 48.86,131.57 50.77,131.57 50.9,131.44 v1(51.4,131.44) 51.53,131.44 52.42,130.56 57.6,130.56 59.51,132.46 65.65,132.46 72.59,139.4 73.5,139.4 76.35,142.24 76.35,143.69 76.93,144.27 76.93,151 79.09,153.16 80.11,153.16 80.49,153.54 80.49,154.56 81.63,155.7 86.58,155.7 87.32,154.97 v5(88.61,154.97) 88.61,157.33 91.81,160.53 97.3,160.53 100.3,157.53 100.3,154.43 101.8,152.93 101.8,149.89 103.1,148.58 103.1,144.64 103.6,144.15 103.6,142.77 102.91,142.09 101.54,142.09 100.78,142.85 98.11,142.85 97.56,143.41 97.56,144.37 97.99,144.81 97.99,146.96 v4(97.83,147.12)
PD6: length 31.3
  TOP w0.127: 48.1,131.44 R53.1 48.74,129.54 v1(48.99,129.54) 49.88,130.43 51.78,130.43 52,130.65 U7.122 ; CN6.24 v1(29.69,122.68)
  BOTTOM w0.127: v1(29.69,122.68) 31.97,122.68 39.59,130.3 46.45,130.3 47.21,129.54 v1(48.99,129.54)
PD7: length 121.1
  TOP w0.127: R18.2 77.69,161.54 75.28,163.96 73.25,163.96 72.49,164.72 72.49,168.4 71.85,169.04 70.58,169.04 69.82,168.28 69.82,167.51 69.06,166.75 65.37,166.75 64.61,167.51 64.61,168.45 63.7,169.37 43.61,169.37 41.12,166.88 41.12,137.54 34.39,130.81 v1(34.39,125.86) ; CN6.23 28.04,122.68 v1(28.16,122.81) ; v1(49.63,129.54) 49.63,129.67 50.01,130.05 51.91,130.05 52.01,130.15 U7.123
  BOTTOM w0.127: v1(49.63,129.54) 49.63,129.59 49.17,130.05 47.21,130.05 46.45,130.81 39.34,130.81 v1(34.39,125.86) 31.85,123.32 29.18,123.32 28.67,122.81 v1(28.16,122.81)
PE4: length 63.1
  TOP w0.127: R84.2 53.69,114.17 54.96,115.44 55.47,115.44 55.98,115.95 v1(55.98,116.08) 55.98,116.59 55.75,116.81 U7.3 ; CN7.21 v1(96.87,123.95)
  BOTTOM w0.127: 53.82,113.03 53.82,113.28 54.45,113.92 55.98,113.92 56.36,114.3 56.36,114.94 55.98,115.32 v1(55.98,116.08) 55.98,117.35 58.13,119.51 58.13,122.07 60.93,124.87 60.93,125.48 62.96,127.51 66.39,127.51 68.55,125.35 78.96,125.35 79.47,125.86 89.5,125.86 91.41,123.95 v1(96.87,123.95)
PE5: length 60.7
  TOP w0.127: U7.4 56.25,116.69 56.61,116.33 56.61,115.95 57.12,115.44 v1(57.12,115.32) 56.86,115.06 55.72,115.06 55.21,114.55 R85.2 ; CN7.23 v1(97,122.68)
  BOTTOM w0.127: v1(97,122.68) 96.62,123.06 90.65,123.06 88.49,125.22 80.11,125.22 79.72,124.84 68.17,124.84 66.14,126.87 63.21,126.87 61.44,125.09 61.44,124.61 58.9,122.07 58.9,119.25 57.63,117.98 57.63,115.95 57.12,115.44 v1(57.12,115.32) 57.13,115.31 57.13,112.98
PE6: length 61.6
  TOP w0.127: CN7.22 v1(98.27,123.95) ; U7.5 56.75,116.7 v1(57.12,116.33) 57.63,115.82 57.63,115.19 56.74,114.3 R86.2
  BOTTOM w0.127: 55.54,113.11 56.74,114.3 56.74,114.94 56.61,115.06 56.61,115.82 v1(57.12,116.33) 57.12,117.98 58.39,119.25 58.39,121.95 61.18,124.74 61.18,125.22 63.09,127.13 66.26,127.13 68.29,125.09 79.47,125.09 79.85,125.48 88.87,125.48 90.9,123.44 97.38,123.44 97.89,123.95 v1(98.27,123.95)
